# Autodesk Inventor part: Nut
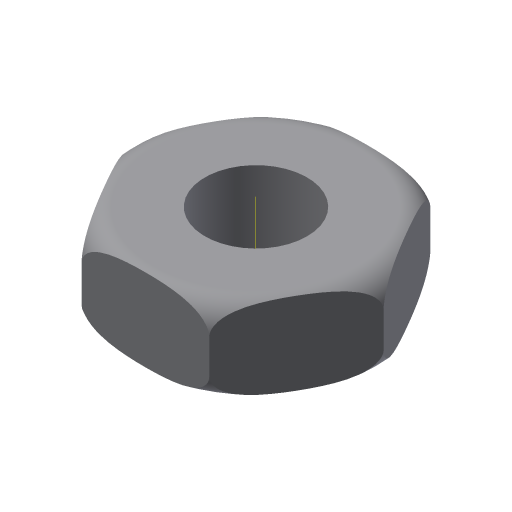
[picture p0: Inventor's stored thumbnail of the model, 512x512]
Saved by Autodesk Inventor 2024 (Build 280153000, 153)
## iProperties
Created: 2009-04
Part Number: Nut
Document SubType Name: Modeling
Designer: Sham
Density: 1 g/cm^3
Material: Generic
Appearance: Default
Author: Sham
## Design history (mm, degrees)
sketch "Sketch1"
  geometry: L1 (7.5, 12.99)-(15, 0); L2 (15, 0)-(7.5, -12.99); L3 (7.5, -12.99)-(-7.5, -12.99); L4 (-7.5, -12.99)-(-15, 0); L5 (-15, 0)-(-7.5, 12.99); L6 (-7.5, 12.99)-(7.5, 12.99); C1 r 6 at (0, 0); 1 further point
  constraints: 12 end point, 1 centre point, 1 coincident, 13 other
  dimensions: "d0" = 30 distance of L1.end L4.end; "d1" = 12 diameter of C1
extrude "Extrusion1" new body sketch "Sketch1" distance "d2" = 12; taper "d3" = 0 deg
sketch "Sketch2"
  geometry: L1 (-12, 0)-(-12, -0.022); L2 (-15, 7)-(-15, 3); L3 (0, -2.87)-(0, 12.87) reference; A1 r 3 centre (-12, 7) between (-12, 10) and (-15, 7); A2 r 3 centre (-12, 3) between (-15, 3) and (-12, 0)
  constraints: 4 end point, 4 point on circle, 2 centre point, 1 tangent
revolve "Revolution1" sketch "Sketch2" stored, may be unused: angle "d7" = 90 deg
body "Solid1"
other parameters: "d6" = 90 deg
